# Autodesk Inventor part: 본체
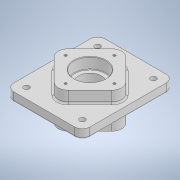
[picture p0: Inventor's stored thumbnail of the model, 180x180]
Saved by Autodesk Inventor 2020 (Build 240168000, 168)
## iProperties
Created: 2021-07
Part Number: 본체
Material: 일반
Document SubType Name: Modeling
Designer: Owner
Density: 1 g/cm^3
Appearance: 기본값
Author: Owner
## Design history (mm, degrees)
sketch "스케치1"
  geometry: L1 (-75, 90)-(75, 90); L2 (75, 90)-(75, -90); L3 (75, -90)-(-75, -90); L4 (-75, -90)-(-75, 90); L5 (-75, 90)-(75, -90); L6 (75, 90)-(-75, -90); 1 further point
  constraints: 12 end point, 2 midpoint, 2 parallel, 1 horizontal, 1 perpendicular
  dimensions: "d0" = 150 distance of L2.end L3.end; "d1" = 180 distance of L1.end L2.end
extrude "돌출1" new body sketch "스케치1" stored distance "d2" = 18; taper "d3" = 0 deg
sketch "스케치2"
  geometry: L1 (-70.711, 0)-(0, 70.711); L2 (0, 70.711)-(70.711, 0); L3 (70.711, 0)-(0, -70.711); L4 (0, -70.711)-(-70.711, 0); L5 (-70.711, 0)-(70.711, 0); L6 (0, 70.711)-(0, -70.711); 1 further point
  constraints: 12 end point, 2 midpoint, 2 parallel, 1 perpendicular, 1 vertical
  dimensions: "d4" = 100 distance of L1.start L1.end; "d5" = 100 distance of L3.end L1.start
extrude "돌출2" join sketch "스케치2" distance "d6" = 23; taper "d7" = 0 deg
node "작업 평면1"
sketch "스케치3"
  geometry: L1 (70.711, 0)-(0, -70.711); L2 (0, -70.711)-(-70.711, 0); L3 (-70.711, 0)-(0, 70.711); L4 (0, 70.711)-(70.711, 0); L5 (70.711, 0)-(-70.711, 0); L6 (0, -70.711)-(0, 70.711); 1 further point
  constraints: 12 end point, 2 midpoint, 2 parallel, 1 horizontal, 1 perpendicular
  dimensions: "d9" = 100 distance of L2.end L3.end; "d10" = 100 distance of L1.end L2.end
extrude "돌출3" join sketch "스케치3" stored distance "d11" = 23; taper "d12" = 0 deg
fillet "모깎기1" dims "d13" = 20
fillet "모깎기2" dims "d14" = 15
sketch "스케치4"
  geometry: C1 r 11 at (-55, 70); C2 r 11 at (55, 70); C3 r 11 at (55, -70); C4 r 11 at (-55, -70); 1 further point
  constraints: 4 centre point, 3 equal radius, 2 horizontal alignment, 2 vertical alignment
  dimensions: "d15" = 110 distance of C1.centre C2.centre; "d16" = 140 distance of C3.centre C2.centre; "d17" = 70 vertical distance of point (0, 0) C2.centre; "d18" = 55 horizontal distance of point (0, 0) C1.centre; "d19" = 22 diameter of C2; "d20" = 22 diameter of C4 (derived)
extrude "돌출4" join sketch "스케치4" distance "d21" = 5; taper "d22" = 0 deg
sketch "스케치5"
  geometry: C1 r 11 at (0, 0) reference; 2 further points
  constraints: 1 coincident
hole "구멍1" sketch "스케치5" at (0, 0) diameter "d23" = 11; stored, may be unused: countersink angle "d27" = 90 deg, drill point angle "d29" = 118 deg; dims "d24" = 6, "d25" = 4, "d26" = 2, "d28" = 8
sketch "스케치6"
  geometry: 2 further points
  constraints: 1 horizontal alignment
  dimensions: "d30" = 48 distance of point (48, 0) point (0, 0)
hole "구멍2" sketch "스케치6" at (48, 0) diameter "d31" = 4.917; stored, may be unused: countersink angle "d35" = 90 deg, drill point angle "d37" = 118 deg; dims "d32" = 10, "d33" = 4, "d34" = 2, "d36" = 13
sketch "스케치7"
  geometry: 2 further points
  constraints: 1 coincident
hole "구멍3" sketch "스케치7" at (0, 0) diameter "d41" = 45; stored, may be unused: countersink angle "d45" = 90 deg, drill point angle "d47" = 118 deg; dims "d42" = 10, "d43" = 62, "d44" = 22, "d46" = 13
fillet "모깎기3" dims "d48" = 1
chamfer "모따기1" distance "d49" = 1; stored, may be unused: second distance "d50" = 2, angle "d51" = 45 deg
fillet "모깎기4" dims "d52" = 3
fillet "모깎기5" dims "d53" = 3
fillet "모깎기6" dims "d54" = 3
sketch "스케치8"
  geometry: 2 further points
  constraints: 1 vertical alignment
  dimensions: "d55" = 48 distance of point (0, 0) point (0, -48)
hole "구멍4" sketch "스케치8" at (0, -48) diameter "d56" = 4.917; stored, may be unused: countersink angle "d60" = 90 deg, drill point angle "d62" = 118 deg; dims "d57" = 10, "d58" = 62, "d59" = 22, "d61" = 13
sketch "스케치9"
  geometry: L1 (60, 90)-(-60, 90) reference; 2 further points
  constraints: 1 vertical alignment, 1 other
  dimensions: "d66" = 15 distance from line of L1 point (0, 75)
feature "엠보싱1" sketch "스케치9" dims "d0" = 150, "d1" = 180, "d67" = 0.5, "d68" = 0
sketch "스케치10"
  geometry: C1 r 22.5 at (0, 0) reference; 2 further points
  constraints: 1 coincident
hole "구멍5" sketch "스케치10" at (0, 0) diameter "d69" = 62; stored, may be unused: countersink angle "d73" = 90 deg, drill point angle "d75" = 0 deg; dims "d70" = 10, "d71" = 62, "d72" = 22, "d74" = 22
chamfer "모따기2" distance "d79" = 1; stored, may be unused: second distance "d80" = 2, angle "d81" = 45 deg
fillet "모깎기7" dims "d85" = 1
node "솔리드1"
mirror "미러1"
mirror "미러2"
pattern_circular "원형 패턴1" dims angle "d39" = 360 deg
pattern_circular "원형 패턴3" dims angle "d77" = 360 deg
feature "A9D066F2-1C7D-4E18-AEED-F7BC21143FA4" dims "d23" = 11, "d24" = 6, "d25" = 4, "d26" = 2, "d27" = 90 deg, "d28" = 8, "d29" = 118 deg
